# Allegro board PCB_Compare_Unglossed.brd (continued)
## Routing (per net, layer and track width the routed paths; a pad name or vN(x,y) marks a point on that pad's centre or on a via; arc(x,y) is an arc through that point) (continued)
RA7: length 136.7
  TOP w0.127: v1(105.41,70.26) U12.29 105.41,72.97 104.9,73.48 104.9,79.17 105.41,79.68 U16.29 105.41,85.67 104.9,86.18 104.9,93.68 105.41,94.18 U17.29 105.41,98.37 104.9,98.88 104.9,107.16 105.41,107.67 U11.29 ; 57.91,87 v1(58.45,86.46) ; 80.64,84.45 v1(80.64,86.18) 80.39,86.18 80.14,86.44 80.14,90.25 80.64,90.75 80.64,98.63 81.15,99.14 81.15,102.39 80.64,102.9 80.64,109.86 ; 80.64,71.75 v1(80.64,68.99)
  INNER_1 w0.127: v1(80.64,86.18) v1(80.64,68.99)
  INNER_2 w0.127: v1(58.45,86.46) 58.95,86.97 77.47,86.97 78.26,86.18 v1(80.64,86.18)
  BOTTOM w0.127: v1(80.64,68.99) 97.36,68.99 98.17,68.17 100.53,68.17 102.62,70.26 v1(105.41,70.26)
RA8: length 166
  TOP w0.127: 59.18,87 v1(59.72,86.46) ; U12.28 106.68,69.52 v1(107.7,68.5) ; v1(106.17,77.39) 106.17,82.17 106.68,82.68 U16.28 ; U10.28 81.91,67.26 v1(81.41,66.75) ; v1(106.68,94.72) U17.28 106.68,98.42 107.19,98.93 107.19,104.83 106.68,105.33 U11.28 ; v1(81.91,81.48) U14.28 81.91,85.85 81.41,86.36 81.41,90.09 81.91,90.6 U13.28 81.91,98.37 82.42,98.88 82.42,105.79 81.91,106.3 U15.28
  INNER_1 w0.127: v1(107.7,68.5) 106.17,70.03 v1(106.17,77.39) 106.68,77.9 v1(106.68,94.72) ; v1(81.41,66.75) 81.91,67.26 v1(81.91,81.48)
  INNER_2 w0.127: v1(81.41,66.75) 81.91,67.26 106.45,67.26 v1(107.7,68.5) ; v1(59.72,86.46) 59.18,85.93 58.45,85.93 57.94,85.42 57.94,82.45 57.99,82.4 57.99,82.37 61.11,79.25 82.93,79.25 83.69,80.01 83.69,80.52 83.44,80.77 82.63,80.77 v1(81.91,81.48)
RA9: length 159
  TOP w0.127: U14.22 89.53,79.78 v1(90.3,79.02) ; v1(88.27,73.46) 89.05,73.46 89.53,72.97 U10.22 ; U5.E8 v1(58.45,88.8) ; U13.22 89.53,98.37 88.95,98.96 v1(88.95,102.31) 89.53,102.9 U15.22 89.53,111.12 89.74,111.33 114.1,111.33 114.3,111.12 U11.22 114.3,107.14 113.79,106.63 113.79,98.88 114.3,98.37 U17.22 114.3,94.69 113.79,94.18 113.79,86.18 114.3,85.67 U16.22 114.3,77.93 113.79,77.42 113.79,73.48 114.3,72.97 U12.22
  BOTTOM w0.127: v1(88.95,102.31) 89.1,102.16 89.1,80.21 v1(90.3,79.02) 90.3,75.49 v1(88.27,73.46) 68.1,73.46 58.95,82.6 58.95,88.29 v1(58.45,88.8)
RA10: length 146.8
  TOP w0.127: U5.E9 v1(59.72,88.8) ; v1(115.93,66.75) 115.93,70.05 115.57,70.41 U12.21 115.57,72.97 115.06,73.48 115.06,76.15 115.57,76.66 U16.21 115.57,85.67 115.06,86.18 115.06,90.63 115.57,91.14 U17.21 115.57,98.65 116.08,99.16 116.08,104.85 115.57,105.36 U11.21 ; U15.21 90.81,105.36 91.31,104.85 91.31,99.14 90.81,98.63 U13.21 90.81,94.28 91.31,93.78 91.31,90.55 v1(90.17,89.41) 90.17,86.33 90.81,85.7 U14.21 v1(90.81,80.9) 91.31,80.39 91.31,73.61 90.81,73.1 U10.21 90.81,67.26 v1(91.31,66.75)
  INNER_2 w0.127: v1(59.72,88.8) 60.71,87.81 89.08,87.81 90.17,88.9 v1(90.17,89.41)
  BOTTOM w0.127: v1(115.93,66.75) v1(91.31,66.75)
RA11: length 171.6
  TOP w0.127: U11.20 116.84,105.36 117.35,104.85 117.35,99.14 116.84,98.63 U17.20 116.84,91.39 117.35,90.88 117.35,86.18 116.84,85.67 U16.20 116.84,76.66 116.33,76.15 116.33,73.48 116.84,72.97 U12.20 v1(116.84,69.8) ; v1(91.82,65.99) 91.85,66.01 91.85,70.31 92.07,70.54 U10.20 ; v1(91.82,79.27) 91.85,79.3 91.85,83.01 92.07,83.24 U14.20 92.07,85.67 91.57,86.18 91.57,90.88 92.07,91.39 U13.20 92.07,98.37 92.58,98.88 92.58,104.85 92.07,105.36 U15.20 ; U5.E10 v1(60.99,88.8)
  INNER_1 w0.127: v1(91.82,65.99) v1(91.82,79.27)
  INNER_2 w0.127: v1(91.82,65.99) 113.03,65.99 v1(116.84,69.8)
  BOTTOM w0.127: v1(60.99,88.8) 60.48,89.31 58.19,89.31 57.94,89.05 57.94,82.35 67.34,72.95 88.52,72.95 91.82,76.25 v1(91.82,79.27)
RA12: length 165.8
  TOP w0.127: v1(117.63,69.88) 118.11,70.36 U12.19 118.11,72.97 117.6,73.48 117.6,82.32 118.11,82.83 U16.19 118.11,85.67 117.6,86.18 117.6,93.68 118.11,94.18 U17.19 118.11,98.37 117.6,98.88 117.6,108.05 118.11,108.56 U11.19 ; v1(93.34,70.31) 93.34,72.77 92.84,73.28 92.84,81.64 93.34,82.14 93.34,85.93 93.85,86.44 93.85,90.68 93.34,91.19 93.34,97.16 92.84,97.16 92.84,107.92 93.34,108.43 93.34,109.86 ; U5.G2 v1(49.76,85.19)
  INNER_2 w0.127: v1(117.63,69.88) 116.18,71.32 96.47,71.32 95.45,70.31 v1(93.34,70.31) 88.67,74.98 50.65,74.98 49.12,76.5 49.12,80.04 51.54,82.45 51.54,83.41 v1(49.76,85.19)
RA13: length 154.5
  TOP w0.127: 50.29,87 v1(49.76,86.46) ; U10.18 94.62,72.97 94.11,73.48 94.11,79.35 v1(93.34,80.11) 94.62,81.38 U14.18 94.62,85.67 94.11,86.18 94.11,90.7 94.62,91.21 U13.18 94.62,98.37 95.12,98.88 95.12,107.92 94.62,108.43 U15.18 ; U12.18 119.38,72.97 118.87,73.48 118.87,80.04 v1(119.38,80.54) U16.18 119.38,85.67 118.87,86.18 118.87,95.43 119.38,95.94 U17.18 119.38,98.6 118.62,99.36 118.62,105.89 119.38,106.65 U11.18
  INNER_2 w0.127: v1(49.76,86.46) 51.79,84.43 51.79,83.67 52.04,83.41 57.18,83.41 57.66,82.93 57.66,82.91 57.68,82.88 57.68,82.3 60.99,78.99 83.82,78.99 84.94,80.11 v1(93.34,80.11) 115.34,80.11 115.77,80.54 v1(119.38,80.54)
RA14: length 164
  TOP w0.127: U5.E2 v1(49.76,88.8) ; v1(95.88,91.49) 94.62,90.22 U13.15 94.62,86.18 95.12,85.67 95.12,79.63 94.62,79.12 U14.15 94.62,73.48 95.12,72.97 95.12,65.71 94.62,65.2 U10.15 ; v1(119.38,104.14) U11.15 119.38,99.01 119.89,98.5 119.89,92.41 119.38,91.9 U17.15 119.38,86.21 119.89,85.7 119.89,78.44 119.38,77.93 U16.15 119.38,73.48 119.89,72.97 119.89,63.96 119.38,63.45 U12.15 ; U15.15 v1(94.62,104.01)
  INNER_1 w0.127: v1(119.38,104.14) 118.87,104.14 118.75,104.01 v1(94.62,104.01)
  INNER_2 w0.127: v1(49.76,88.8) 50.52,89.56 51.26,89.56 53.04,91.34 53.04,91.57 53.57,92.1 95.28,92.1 v1(95.88,91.49)
  BOTTOM w0.127: v1(94.62,104.01) 94.62,92.76 v1(95.88,91.49)
RA15: length 163.8
  TOP w0.127: 93.34,100.33 v1(93.34,98.68) ; U11.14 118.11,98.96 118.62,98.45 118.62,93.42 118.11,92.91 U17.14 118.11,86.18 118.62,85.67 118.62,82.07 118.11,81.56 U16.14 118.11,73.48 118.62,72.97 118.62,64.24 118.11,63.73 U12.14 v1(118.11,60.71) ; v1(92.84,86.18) 93.22,86.18 93.34,86.31 93.34,87.63 ; v1(93.34,60.32) v1(93.34,64.64) 93.85,65.15 93.85,73.02 93.34,73.53 v1(93.34,79.38) ; U5.D2 v1(49.76,90.07)
  INNER_1 w0.127: v1(93.34,98.68) 85.19,106.83 76.99,106.83 63.27,93.12 56.52,93.12 54.23,90.83 50.52,90.83 v1(49.76,90.07) ; v1(93.34,79.38) 92.84,79.88 v1(92.84,86.18) ; v1(93.34,60.32) 93.73,59.94 105.66,59.94 106.81,61.09 117.73,61.09 v1(118.11,60.71)
  BOTTOM w0.127: v1(93.34,98.68) 92.84,98.17 v1(92.84,86.18)
RCS0: length 44.9
  TOP w0.127: v1(83.19,80.26) 83.19,73.66 82.68,73.15 82.68,67.77 83.19,67.26 83.19,62.23 ; U5.J8 v1(58.45,82.65)
  INNER_2 w0.127: v1(58.45,82.65) 60.83,80.26 v1(83.19,80.26)
RCS1: length 66.5
  TOP w0.127: U5.J9 v1(59.72,82.65) ; U11.6 v1(107.95,101.78) ; 83.19,100.33 v1(83.19,101.78)
  INNER_2 w0.127: v1(83.19,101.78) 83.95,101.02 107.19,101.02 v1(107.95,101.78)
  BOTTOM w0.127: v1(59.72,82.65) 60.48,83.41 75.18,83.41 77.11,85.34 77.17,85.34 77.6,85.78 77.6,85.83 81.41,89.64 81.41,100 v1(83.19,101.78)
RCS2: length 68.3
  TOP w0.127: v1(107.95,80.62) U16.6 107.95,73.48 108.46,72.97 108.46,66.47 107.95,65.96 U12.6 ; U5.J10 v1(60.99,82.65)
  INNER_2 w0.127: v1(107.95,80.62) 99.95,80.62 98.93,81.64 82.6,81.64 82.25,81.99 81.64,81.99 80.52,80.87 76.63,80.87 74.85,82.65 v1(60.99,82.65)
RCS3: length 62.3
  TOP w0.127: U17.6 v1(107.95,89.08) ; 51.56,87 v1(51.03,86.46) ; 83.19,87.63 v1(83.19,89.08)
  INNER_1 w0.127: v1(51.03,86.46) 51.82,87.25 68.94,87.25 v1(70.23,88.54)
  INNER_2 w0.127: v1(107.95,89.08) 92.13,89.08 91.29,89.92 89.97,89.92 89.64,89.59 83.69,89.59 v1(83.19,89.08) 82.65,88.54 v1(70.23,88.54)
RD0: length 111.1
  TOP w0.127: v1(109.22,82.04) U16.26 109.22,85.67 109.98,86.44 109.98,90.22 109.22,90.98 U17.26 ; U14.26 v1(84.45,83.01) ; U15.26 v1(84.45,108.41) ; 49.02,87 v1(48.49,86.46)
  INNER_1 w0.127: v1(65.05,79.76) 61.39,83.41 58.19,83.41 57.94,83.67 57.94,83.92 57.18,84.68 49.5,84.68 49.25,84.94 49.25,85.7 v1(48.49,86.46)
  INNER_2 w0.127: v1(109.22,82.04) 85.42,82.04 v1(84.45,83.01)
  BOTTOM w0.127: v1(84.45,108.41) 83.95,107.9 83.95,83.52 v1(84.45,83.01) 81.2,79.76 v1(65.05,79.76)
RD1: length 117.2
  TOP w0.127: v1(113.03,82.3) U16.23 113.03,85.67 112.32,86.39 112.32,90.35 113.03,91.06 U17.23 ; U5.E1 v1(48.49,88.8) ; U15.23 v1(88.27,108.41) ; U14.23 v1(88.27,83.01)
  INNER_1 w0.127: v1(82.93,85.9) 81.41,87.43 81.41,90.07 79.63,91.85 57.99,91.85 55.45,89.31 49.56,89.31 49.05,88.8 v1(48.49,88.8)
  INNER_2 w0.127: v1(82.93,85.9) 85.37,85.9 v1(88.27,83.01) 89.03,83.77 108.71,83.77 110.57,81.91 112.65,81.91 v1(113.03,82.3)
  BOTTOM w0.127: v1(88.27,83.01) 87.76,83.52 87.76,107.9 v1(88.27,108.41)
RD2: length 113.2
  TOP w0.127: U15.10 v1(88.27,101.78) ; U14.10 v1(88.27,76.38) ; U16.10 113.03,77.5 112.67,77.85 v1(112.67,78.51) 113.54,79.38 113.54,85.67 113.03,86.18 U17.10 ; U5.D1 v1(48.49,90.07)
  INNER_1 w0.127: v1(48.49,90.07) 49.05,90.07 49.56,89.56 55.09,89.56 57.63,92.1 78.59,92.1 v1(88.27,101.78)
  INNER_2 w0.127: v1(112.67,78.51) 111.23,78.51 109.09,76.38 v1(88.27,76.38)
  BOTTOM w0.127: v1(88.27,76.38) 88.77,76.89 88.77,101.27 v1(88.27,101.78)
RD3: length 108.3
  TOP w0.127: U15.7 v1(84.45,101.78) ; U5.H1 v1(48.49,83.92) ; U17.7 109.22,86.18 108.71,85.67 108.71,79.17 108.86,79.02 v1(108.86,78.51) 108.86,77.34 109.22,76.99 U16.7 ; U14.7 v1(84.45,76.38)
  INNER_1 w0.127: v1(76.23,78) 60.99,78 55.4,83.59 55.4,84.12 55.68,84.4 55.68,84.43 49,84.43 v1(48.49,83.92)
  INNER_2 w0.127: v1(108.86,78.51) 86.59,78.51 v1(84.45,76.38) 82.83,78 v1(76.23,78)
  BOTTOM w0.127: v1(84.45,76.38) 84.96,76.89 84.96,101.27 v1(84.45,101.78)
RD4: length 128.8
  TOP w0.127: U10.26 v1(84.45,70.31) ; U11.26 v1(109.22,108.41) ; U13.26 v1(84.45,95.71) ; U5.A1 v1(48.49,93.88) ; U12.26 v1(109.22,70.31)
  INNER_1 w0.127: v1(84.45,70.31) 83.95,70.82 83.95,95.2 v1(84.45,95.71)
  INNER_2 w0.127: v1(109.22,108.41) 108.71,107.9 108.71,101.73 106.17,99.19 87.93,99.19 v1(84.45,95.71) 83.69,96.47 51.08,96.47 v1(48.49,93.88) ; v1(84.45,70.31) 85.27,69.49 108.41,69.49 v1(109.22,70.31)
RD5: length 131
  TOP w0.127: U5.A2 v1(49.76,93.88) ; U11.23 v1(113.03,108.41) ; U10.23 v1(88.27,70.31) ; U12.23 v1(113.03,70.31) ; U13.23 v1(88.27,95.71)
  INNER_1 w0.127: v1(88.27,95.71) 87.76,95.2 87.76,70.82 v1(88.27,70.31)
  INNER_2 w0.127: v1(113.03,108.41) 112.52,107.9 112.52,101.8 106.93,96.22 88.77,96.22 v1(88.27,95.71) 87.3,94.74 50.62,94.74 v1(49.76,93.88) ; v1(88.27,70.31) 92.13,70.31 92.63,69.8 95.5,69.8 96.77,71.07 112.27,71.07 v1(113.03,70.31)
RD6: length 129.2
  TOP w0.127: U13.10 v1(88.27,89.08) ; U12.10 v1(113.03,63.68) ; U5.A3 v1(51.03,93.88) ; U10.10 v1(88.27,63.68) ; U11.10 v1(113.03,101.78)
  INNER_1 w0.127: v1(88.27,63.68) 89.03,64.44 89.03,88.32 v1(88.27,89.08) v1(88.27,94.64)
  INNER_2 w0.127: v1(88.27,63.68) 89.03,62.92 112.27,62.92 v1(113.03,63.68) ; v1(51.03,93.88) 51.56,94.41 87.53,94.41 87.78,94.64 v1(88.27,94.64) 88.77,94.13 105.38,94.13 v1(113.03,101.78)
RD7: length 124.6
  TOP w0.127: U10.7 v1(84.45,63.68) ; U13.7 v1(84.45,89.08) ; U12.7 v1(109.22,63.68) ; U5.A4 v1(52.3,93.88) ; U11.7 v1(109.22,101.78)
  INNER_1 w0.127: v1(84.45,63.68) 84.96,64.19 84.96,88.57 v1(84.45,89.08) v1(84.45,93.8) 85.17,94.51 85.17,95.96 86.44,97.23 104.67,97.23 v1(109.22,101.78)
  INNER_2 w0.127: v1(84.45,93.8) 84,93.34 60.78,93.34 60.76,93.37 53.37,93.37 52.86,93.88 v1(52.3,93.88) ; v1(84.45,63.68) 85.98,65.2 107.7,65.2 v1(109.22,63.68)
RDY: length 39.9
  INNER_2 w0.127: J1.50 23.55,60.96 25.32,62.74 38.84,62.74 43.92,57.66 43.92,57.05 U2.23
RESET: length 72.1
  TOP w0.127: U5.B5 v1(53.57,92.61)
  BOTTOM w0.127: J1.53 16.48,72.36 16.48,95.35 21.82,100.69 46.2,100.69 53.06,93.83 53.06,93.12 v1(53.57,92.61)
RWE: length 151.3
  TOP w0.127: v1(114.3,60.58) U12.11 114.3,63.5 114.91,64.11 114.91,72.75 114.3,73.36 U16.11 114.3,76.66 114.81,77.17 114.81,85.67 114.3,86.18 U17.11 114.3,92.66 114.81,93.17 114.81,98.37 114.3,98.88 U11.11 ; U15.11 89.53,98.88 90.04,98.37 90.04,92 v1(90.55,91.49) 89.53,90.47 U13.11 89.53,86.18 89.03,85.67 89.03,77.67 89.53,77.17 U14.11 89.53,73.63 90.04,73.13 90.04,63.96 89.53,63.45 U10.11 v1(89.53,60.32) ; U5.H5 v1(53.57,83.92)
  INNER_1 w0.127: v1(89.53,60.32) 90.17,59.69 105.89,59.69 106.78,60.58 v1(114.3,60.58)
  INNER_2 w0.127: v1(90.55,91.49) 90.2,91.85 58.14,91.85 54.84,88.54 54.84,85.19 v1(53.57,83.92)
SEL: length 66.8
  TOP w0.127: U5.B3 v1(51.03,92.61)
  INNER_1 w0.127: v1(51.03,92.61) 50.52,92.1 48.51,92.1 45.97,89.56 45.97,32.13 U2.14
V+12: length 200.9
  TOP w0.203: 71.88,36.2 90.3,36.2
  TOP w0.381: U19.4 v1(104.32,40) ; U23.4 v1(104.32,20.32) 105.21,20.32 105.97,19.56 105.97,19.13 U20.7 ; 90.3,36.2 95.25,36.2 95.88,36.83 107.31,36.83 ; J1.63 J1.64 12.7,96.62 14.5,98.42 59.97,98.42 69.09,89.31 69.09,37.46 70.36,36.2 71.88,36.2
  INNER_1 w0.381: v1(102.62,27.3) 104.32,25.6 v1(104.32,20.32)
  INNER_2 w0.381: 107.31,36.83 105.46,38.68 105.46,38.86 v1(104.32,40)
  BOTTOM w0.381: C28.1 v1(102.62,8.25) 103.35,8.99 103.35,19.35 v1(104.32,20.32) ; C25.1 v1(102.62,27.3) 102.62,32.13 107.31,36.83
VCLKA: length 86.8
  TOP w0.203: U8.11 v1(74.78,29.21) ; U18.11 v1(77.62,40.64) ; U5.J4 v1(52.3,82.65) ; U21.11 v1(78.26,20.32)
  INNER_1 w0.203: v1(78.26,20.32) 78.26,23.11 74.78,26.59 v1(74.78,29.21) 76.1,30.53 76.1,39.12 v1(77.62,40.64) 75.23,43.03 64.49,43.03 52.3,55.22 v1(52.3,82.65)
VCLKC: length 90.1
  TOP w0.127: U9.11 v1(71.86,8.89)
  INNER_1 w0.127: v1(71.86,8.89) 71.09,9.65 57.78,9.65 45.08,22.35 v1(45.08,77.47)
  BOTTOM w0.127: R5.2 v1(45.08,77.47)
VD0: length 103.2
  TOP w0.127: v1(49.91,21.59) 52.45,19.05 U9.2 65.53,19.05 66.67,20.19 66.67,22.61 64.77,24.51 63.25,24.51 60.71,27.05 60.71,37.26 62.81,39.37 U8.2 65.53,39.37 66.17,40 66.17,41.02 64.39,42.8 62.36,42.8 60.83,44.32 60.83,53.98 62.74,55.88 U6.2 65.53,55.88 66.42,56.77 66.42,58.93 50.29,75.06 U5.K2
  BOTTOM w0.127: R9.2 v1(49.91,21.59)
VD1: length 103.5
  TOP w0.127: U5.K3 51.56,74.17 66.67,59.05 66.67,55.75 65.53,54.61 U6.3 62.87,54.61 61.09,52.83 61.09,44.45 62.48,43.05 64.52,43.05 66.42,41.15 66.42,38.99 65.53,38.1 U8.3 62.81,38.1 60.96,36.25 60.96,27.18 63.37,24.77 64.9,24.77 66.93,22.73 66.93,19.18 65.53,17.78 U9.3 51.05,17.78 v1(49.78,19.05)
  BOTTOM w0.127: R13.2 v1(49.78,19.05)
VD2: length 103.9
  TOP w0.127: U5.K4 52.83,73.28 66.93,59.18 66.93,54.74 65.53,53.34 U6.4 62.87,53.34 61.34,51.82 61.34,44.58 62.61,43.31 64.64,43.31 66.67,41.27 66.67,37.97 65.53,36.83 U8.4 62.81,36.83 61.21,35.23 61.21,27.3 63.5,25.02 65.02,25.02 67.18,22.86 67.18,18.16 65.53,16.51 U9.4 v1(49.78,16.51)
  BOTTOM w0.127: R8.2 v1(49.78,16.51)
VD3: length 105.4
  TOP w0.127: v1(49.91,13.97) 51.18,15.24 U9.5 65.53,15.24 67.44,17.14 67.44,22.99 65.15,25.27 63.63,25.27 61.47,27.43 61.47,34.16 62.87,35.56 U8.5 65.53,35.56 66.93,36.96 66.93,41.4 64.77,43.56 62.74,43.56 61.59,44.7 61.59,50.8 62.87,52.07 U6.5 65.53,52.07 67.18,53.72 67.18,59.31 54.1,72.39 U5.K5
  BOTTOM w0.127: R12.2 v1(49.91,13.97)
VD4: length 106.9
  TOP w0.127: v1(49.78,11.43) 52.32,13.97 U9.6 65.53,13.97 67.69,16.13 67.69,23.11 65.28,25.53 63.75,25.53 61.72,27.56 61.72,33.15 62.87,34.29 U8.6 65.53,34.29 67.18,35.94 67.18,41.53 64.9,43.81 62.87,43.81 61.85,44.83 61.85,49.78 62.87,50.8 U6.6 65.53,50.8 67.44,52.7 67.44,59.44 55.37,71.5 U5.K6
  BOTTOM w0.127: R7.2 v1(49.78,11.43)
VD5: length 108.4
  TOP w0.127: U5.K7 56.64,70.61 67.69,59.56 67.69,51.69 65.53,49.53 U6.7 62.87,49.53 62.1,48.77 62.1,44.96 62.99,44.07 65.02,44.07 67.44,41.66 67.44,34.92 65.53,33.02 U8.7 62.87,33.02 61.98,32.13 61.98,27.69 63.88,25.78 65.41,25.78 67.94,23.24 67.94,15.11 65.53,12.7 U9.7 53.59,12.7 v1(49.78,8.89)
  BOTTOM w0.127: R11.2 v1(49.78,8.89)
VD6: length 109.9
  TOP w0.127: U5.K8 57.91,69.72 67.94,59.69 67.94,50.67 65.53,48.26 U6.8 62.87,48.26 62.36,47.75 62.36,45.09 63.12,44.32 65.15,44.32 67.69,41.78 67.69,33.91 65.53,31.75 U8.8 62.74,31.75 62.23,31.24 62.23,27.81 64.01,26.03 65.53,26.03 68.2,23.37 68.2,14.1 65.53,11.43 U9.8 54.86,11.43 v1(49.78,6.35)
  BOTTOM w0.127: R6.2 v1(49.78,6.35)
VD7: length 111.2
  TOP w0.127: v1(49.78,3.81) 56.13,10.16 U9.9 65.53,10.16 68.45,13.08 68.45,23.49 65.66,26.29 64.13,26.29 62.48,27.94 62.48,30.1 62.87,30.48 U8.9 65.53,30.48 67.94,32.89 67.94,41.91 65.28,44.58 63.25,44.58 62.61,45.21 62.61,46.61 62.99,46.99 U6.9 65.53,46.99 68.2,49.66 68.2,59.82 59.18,68.83 U5.K9
  BOTTOM w0.127: R10.2 v1(49.78,3.81)
VREF: length 34.7
  TOP w0.127: L5.1 113.44,5.94 102.84,5.94 v1(101.98,5.08) R14.1
  INNER_1 w0.127: L5.1 115.16,5.94 115.16,23.27 L3.1
WAIT: length 47
  TOP w0.127: U5.J3 v1(51.03,82.65)
  INNER_2 w0.127: J1.51 31.88,63.5 v1(51.03,82.65)
WSTAT: length 54.8
  TOP w0.127: U6.11 v1(74.78,45.72) ; U5.H4 v1(52.3,83.92)
  INNER_1 w0.127: v1(52.3,83.92) 52.86,83.36 52.86,58.93 65.56,46.23 74.27,46.23 v1(74.78,45.72)
N00036: length 35.6
  TOP w0.127: v1(101.45,30.48) 103.99,27.94 L4.2 ; U18.5 v1(89.71,34.29) ; U18.8 v1(89.71,38.1) 92.07,38.1 93.98,40 v1(96.44,40) U19.5
  INNER_1 w0.127: v1(89.71,38.1) 90.22,37.59 90.22,34.8 v1(89.71,34.29) ; v1(101.45,30.48) v1(101.45,33.02) 101.45,35 v1(96.44,40)
  BOTTOM w0.127: R15.1 v1(101.45,30.48) ; R16.1 v1(101.45,33.02)
N00038: length 29.2
  TOP w0.127: U18.4 v1(89.71,33.02)
  INNER_2 w0.127: v1(83.82,31.55) 85.29,33.02 v1(89.71,33.02) 97.97,24.77 L3.2
  BOTTOM w0.127: C24.1 v1(83.82,31.55)
N00044: length 36.8
  TOP w0.127: U19.1 v1(104.32,36.2)
  INNER_1 w0.127: v1(104.32,36.2) 104.83,35.69 104.83,11.96 106.48,10.31 108.36,10.31 112.29,14.25 U20.2
N00060: length 37.4
  TOP w0.127: U18.6 v1(89.71,35.56)
  INNER_2 w0.127: v1(89.71,35.56) 102.84,35.56 106.91,31.5 106.91,30.12 113.28,23.75 113.28,17.4 U20.3
N14843: length 3.2
  BOTTOM w0.127: C13.1 R12.1
N14849: length 3.2
  BOTTOM w0.127: C9.1 R8.1
N14853: length 3.2
  BOTTOM w0.127: C14.1 R13.1
N14855: length 4.4
  BOTTOM w0.127: C10.1 43.87,21.59 43.99,21.72 43.99,22.23 44.12,22.35 44.37,22.35 44.5,22.23 44.5,21.72 44.63,21.59 R9.1
N15143: length 3.2
  BOTTOM w0.127: C11.1 R10.1
N15151: length 3.2
  BOTTOM w0.127: C7.1 R6.1
N15155: length 3.2
  BOTTOM w0.127: C12.1 R11.1
N15161: length 3.2
  BOTTOM w0.127: C8.1 R7.1
N58063: length 5.7
  TOP w0.127: U8.19 U18.12
N58118: length 5.7
  TOP w0.127: U8.18 U18.13
N58173: length 5.7
  TOP w0.127: U8.17 U18.14
N58228: length 5.7
  TOP w0.127: U8.16 U18.15
N58283: length 5.7
  TOP w0.127: U8.15 U18.16
N58338: length 5.7
  TOP w0.127: U8.14 U18.17
N58393: length 5.7
  TOP w0.127: U8.13 U18.18
N58448: length 5.7
  TOP w0.127: U8.12 U18.19
N58834: length 6.4
  TOP w0.127: U9.19 U21.12
N58889: length 6.4
  TOP w0.127: U9.18 U21.13
N58944: length 6.4
  TOP w0.127: U9.17 U21.14
N58999: length 6.4
  TOP w0.127: U9.16 U21.15
N59054: length 6.4
  TOP w0.127: U9.15 U21.16
N59109: length 6.4
  TOP w0.127: U9.14 U21.17
N59164: length 6.4
  TOP w0.127: U9.13 U21.18
N59219: length 6.4
  TOP w0.127: U9.12 U21.19
N282866: length 6
  TOP w0.127: U19.8 v1(96.44,36.2)
  INNER_1 w0.127: v1(96.9,33.02) 96.95,33.07 96.95,35.69 v1(96.44,36.2)
  BOTTOM w0.127: R16.2 v1(96.9,33.02)
N282912: length 14.1
  TOP w0.127: U19.2 v1(104.32,37.46)
  BOTTOM w0.127: v1(104.32,37.46) 103,37.46 99.19,33.66 99.19,32.33 98.55,31.7 97.41,31.7 96.9,31.19 v1(96.9,30.48) R15.2
N409523: length 11.5
  TOP w0.127: U5.J7 57.15,82.68 v1(57.15,82.63)
  INNER_2 w0.127: v1(57.15,82.63) 51.99,77.47 v1(49.68,77.47)
  BOTTOM w0.127: R5.1 v1(49.68,77.47)

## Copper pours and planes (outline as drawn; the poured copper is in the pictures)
GND on GND: 23.44,1.37 22.96,1.85 22.96,6.45 1.85,6.45 1.37,6.93 1.37,107.37 1.85,107.85 22.96,107.85 22.96,112.45 23.44,112.93 123.88,112.93 124.36,112.45 124.36,1.85 123.88,1.37
V12N on VCC: 115.77,1.37 115.77,14.94 114.63,16.05 111.84,16.05 106.12,21.79 100.89,21.79 100.13,21.03 100.13,17.22 99.62,16.71 95.96,16.71 95.45,17.22 95.45,25.07 95.96,25.6 103.96,25.6 104.6,26.21 104.6,28.27 103.96,28.91 95.83,28.91 95.45,29.29 95.45,37.39 95.96,37.9 97.08,37.9 97.59,37.39 97.59,35.48 98.35,34.75 109.3,34.75 110.03,35.48 110.03,41.1 113.59,41.1 114.76,39.93 114.76,30.56 114.22,30.02 112.95,30.02 112.22,29.29 112.22,26.59 112.95,25.86 124.36,25.86 124.36,1.85 123.88,1.37
VCC on VCC: 23.44,1.37 22.96,1.85 22.96,6.45 1.85,6.45 1.37,6.93 1.37,107.37 1.85,107.85 22.96,107.85 22.96,112.45 23.44,112.93 123.88,112.93 124.36,112.45 124.36,26.21 113.11,26.21 112.57,26.75 112.57,29.13 113.11,29.67 114.38,29.67 115.11,30.4 115.11,40.08 113.74,41.45 93.27,41.45 92.51,40.72 92.51,10.72 95.81,7.42 103.58,7.42 105.49,9.35 115.37,9.35 115.37,1.37
V+12 on VCC: 95.96,7.82 92.91,10.87 92.91,40.56 93.42,41.1 109.68,41.1 109.68,35.64 109.14,35.1 98.5,35.1 97.99,35.64 97.99,37.54 97.23,38.3 95.81,38.3 95.05,37.54 95.05,29.13 95.68,28.5 103.81,28.5 104.19,28.12 104.19,26.37 103.81,25.96 95.81,25.96 95.05,25.22 95.05,17.07 95.81,16.31 99.77,16.31 100.53,17.07 100.53,20.88 101.04,21.39 105.97,21.39 111.68,15.7 114.48,15.7 115.37,14.78 115.37,9.7 105.33,9.7 103.43,7.82

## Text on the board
XSECTION_CHART: *  SURFACE - AIR 0 MIL | L1: TOP CONDUCTOR - COPPER 1 MIL | *  DIELECTRIC - FR-4 8 MIL | L2: GND PLANE - COPPER 1 MIL | L3: INNER_1 CONDUCTOR - COPPER 1 MIL | L4: INNER_2 CONDUCTOR - COPPER 1 MIL | L5: VCC PLANE - COPPER 1 MIL | L6: BOTTOM CONDUCTOR - COPPER 1 MIL | DESIGN CROSS SECTION CHART | ___________________________ | TOTAL THICKNESS 46 MIL | 1-6 | FIGURE | SIZE | 13.0 | 31.0 | 38.0 | 75.0 | 110.0 | DRILL CHART: TOP to BOTTOM | ALL UNITS ARE IN MILS | PLATED | NON-PLATED | QTY | 492 | 12 | 122 | 8 | 5
